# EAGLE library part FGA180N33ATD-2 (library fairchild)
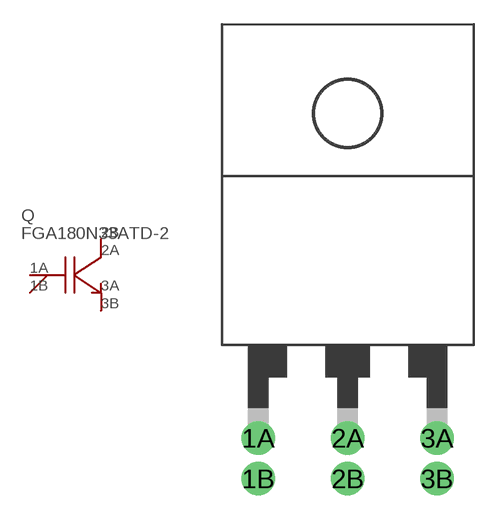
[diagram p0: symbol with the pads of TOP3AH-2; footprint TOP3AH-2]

Designator prefix Q

## FGA180N33ATD-2  [TOP3AH-2]
1A  1A
1B  1B
2A  2A
2B  2B
3A  3A
3B  3B

## Footprint TOP3AH-2 (pad centres in mm)
drill 1.397 round: 1A -5.588,-7.62; 1B -5.588,-10.16; 2A 0,-7.62; 2B 0,-10.16; 3A 5.588,-7.62; 3B 5.588,-10.16
hole 4.115 at 0,12.7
